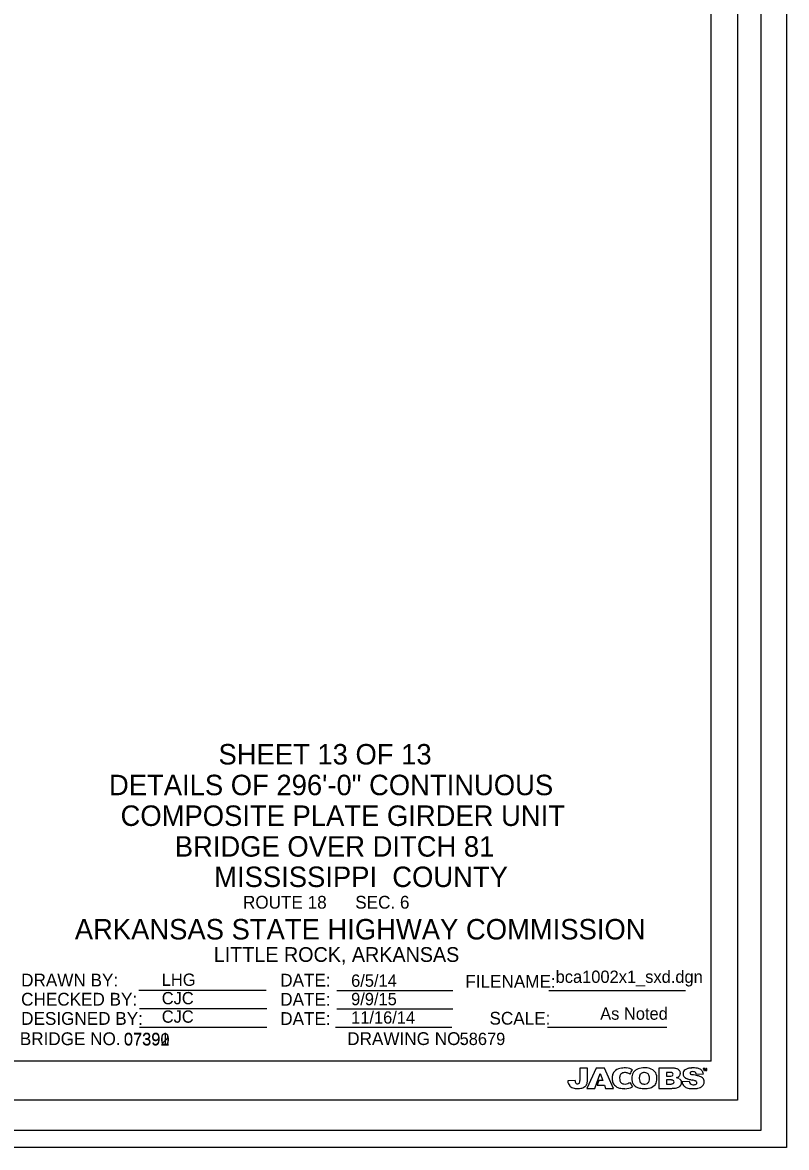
# Model space of a CAD drawing. Extents: x -1771525.9 to -1771483.9, y -422628.9 to -422606.9.
# Drawn here: x -1771498.88 to -1771491.42, y -422628.88 to -422617.89 of the extents above; entities that cross this region are included whole.
import ezdxf

# ---------------------------------------------------------------- set-up
doc = ezdxf.new("R2010")
doc.units = 0
for name, color, linetype in [('border', 7, 'Continuous'), ('Border 2660-Hwy18 - Level 62', 7, 'Continuous'), ('Border 2660-Hwy18 - Level 63', 7, 'Continuous'), ('Border 2660-Hwy18 - Text', 7, 'Continuous'), ('Border 2660-Hwy18 - Title Text', 7, 'Continuous'), ('Bridge No BLFR', 7, 'Continuous'), ('Bridge No BLO', 7, 'Continuous'), ('Bridge No Ditch 81', 7, 'Continuous'), ('Level 62 PDF', 7, 'Continuous'), ('Text', 7, 'Continuous'), ('Title Block Text', 7, 'Continuous'), ('Title Text', 7, 'Continuous')]:
    doc.layers.add(name, color=color, linetype=linetype)

msp = doc.modelspace()

# ---------------------------------------------------------------- linework, layer by layer
at = {"layer": 'border'}
for p, q in [((-1771492.157, -422628.038), (-1771492.157, -422607.492)), ((-1771497.744, -422627.346), (-1771496.501, -422627.346)), ((-1771495.811, -422627.348), (-1771494.677, -422627.348)), ((-1771493.741, -422627.348), (-1771492.405, -422627.348)), ((-1771497.737, -422627.526), (-1771496.494, -422627.526)), ((-1771495.811, -422627.528), (-1771494.677, -422627.528)), ((-1771497.737, -422627.706), (-1771496.494, -422627.706)), ((-1771495.822, -422627.708), (-1771494.688, -422627.708)), ((-1771493.754, -422627.708), (-1771492.588, -422627.708)), ((-1771492.157, -422628.038), (-1771524.168, -422628.038))]:
    msp.add_line(p, q, dxfattribs=at)
for points in [[(-1771493.362, -422628.217), (-1771493.362, -422628.107), (-1771493.437, -422628.107), (-1771493.437, -422628.228)], [(-1771493.24, -422628.16), (-1771493.214, -422628.23), (-1771493.252, -422628.23), (-1771493.268, -422628.273), (-1771493.198, -422628.273), (-1771493.186, -422628.305), (-1771493.109, -422628.305), (-1771493.198, -422628.109), (-1771493.279, -422628.109), (-1771493.369, -422628.305), (-1771493.293, -422628.305), (-1771493.24, -422628.16)], [(-1771492.523, -422628.109), (-1771492.665, -422628.109), (-1771492.665, -422628.305)], [(-1771492.558, -422628.149), (-1771492.591, -422628.149), (-1771492.591, -422628.186)], [(-1771492.3, -422628.167), (-1771492.23, -422628.164)], [(-1771492.219, -422628.111), (-1771492.234, -422628.111), (-1771492.234, -422628.113), (-1771492.228, -422628.113), (-1771492.228, -422628.13), (-1771492.225, -422628.13), (-1771492.225, -422628.113), (-1771492.219, -422628.113), (-1771492.219, -422628.111)], [(-1771492.214, -422628.114), (-1771492.214, -422628.114), (-1771492.208, -422628.13), (-1771492.206, -422628.13), (-1771492.2, -422628.114), (-1771492.2, -422628.114), (-1771492.2, -422628.13), (-1771492.198, -422628.13), (-1771492.198, -422628.111), (-1771492.201, -422628.111), (-1771492.207, -422628.127), (-1771492.213, -422628.111), (-1771492.217, -422628.111), (-1771492.217, -422628.13), (-1771492.214, -422628.13), (-1771492.214, -422628.114)], [(-1771493.484, -422628.229), (-1771493.555, -422628.232)], [(-1771492.591, -422628.186), (-1771492.557, -422628.186)], [(-1771492.554, -422628.223), (-1771492.591, -422628.223), (-1771492.591, -422628.263)], [(-1771492.591, -422628.263), (-1771492.553, -422628.263)], [(-1771492.369, -422628.237), (-1771492.439, -422628.24)], [(-1771492.665, -422628.305), (-1771492.538, -422628.305)]]:
    msp.add_lwpolyline(points, dxfattribs=at)
for centre, radius, start, end in [((-1771493.024, -422628.202), 0.0987, 155.2444, 178.6811), ((-1771493.04, -422628.194), 0.0809, 126.8513, 155.2444), ((-1771493.021, -422628.221), 0.114, 94.7853, 126.8513), ((-1771492.946, -422628.209), 0.104, 161.2834, 178.6702), ((-1771493.021, -422628.184), 0.0243, 134.3139, 161.2834), ((-1771492.999, -422628.206), 0.0556, 110.7655, 134.3139), ((-1771493, -422628.469), 0.363, 86.903, 94.7853), ((-1771493, -422628.204), 0.0529, 91.5073, 110.7655), ((-1771492.998, -422628.267), 0.116, 82.6359, 91.5073), ((-1771492.99, -422628.201), 0.0493, 65.5548, 82.6359), ((-1771492.986, -422628.219), 0.113, 56.9246, 86.903), ((-1771493.019, -422628.264), 0.119, 54.6002, 65.5548), ((-1771492.7, -422628.284), 0.276, 144.635, 154.8844), ((-1771492.831, -422628.205), 0.1, 148.6249, 181.2859), ((-1771492.853, -422628.192), 0.0755, 123.8806, 148.6249), ((-1771492.816, -422628.247), 0.142, 111.7104, 123.8806), ((-1771492.828, -422628.217), 0.109, 96.5371, 111.7104), ((-1771492.766, -422628.207), 0.0917, 160.8611, 181.2981), ((-1771492.826, -422628.186), 0.0287, 136.1177, 160.8611), ((-1771492.809, -422628.203), 0.0518, 117.7176, 136.1177), ((-1771492.796, -422628.489), 0.384, 91.9058, 96.5371), ((-1771492.815, -422628.191), 0.0382, 100.2108, 117.7176), ((-1771492.806, -422628.241), 0.0895, 90.9675, 100.2108), ((-1771492.802, -422628.271), 0.166, 73.4477, 92.4253), ((-1771492.807, -422628.214), 0.0622, 67.077, 90.4218), ((-1771492.798, -422628.192), 0.0386, 24.6274, 67.077), ((-1771492.814, -422628.199), 0.056, 2.7442, 24.6274), ((-1771492.787, -422628.22), 0.112, 41.1934, 73.4477), ((-1771492.746, -422628.184), 0.0579, 18.6966, 41.1934), ((-1771492.815, -422628.207), 0.13, 344.5708, 18.6966), ((-1771492.56, -422628.284), 0.135, 86.2098, 89.3498), ((-1771492.554, -422628.2), 0.0514, 74.8723, 86.2098), ((-1771492.546, -422628.169), 0.0196, 40.2425, 74.8723), ((-1771492.546, -422628.165), 0.0196, 284.1438, 307.8865), ((-1771492.543, -422628.168), 0.0149, 307.8866, 341.4625), ((-1771492.539, -422628.164), 0.0108, 21.9604, 40.2425), ((-1771492.547, -422628.167), 0.0195, 341.4625, 21.9604), ((-1771492.523, -422628.213), 0.104, 72.1885, 90.1477), ((-1771492.51, -422628.171), 0.0603, 61.4844, 72.1885), ((-1771492.508, -422628.168), 0.0564, 34.7868, 61.4844), ((-1771492.501, -422628.153), 0.0471, 296.8412, 329.8182), ((-1771492.488, -422628.154), 0.0315, 16.9455, 34.7868), ((-1771492.487, -422628.161), 0.0307, 329.8182, 347.0949), ((-1771492.501, -422628.158), 0.0455, 347.0949, 16.9455), ((-1771492.383, -422628.164), 0.0476, 124.08, 177.6485), ((-1771492.389, -422628.164), 0.0416, 177.6485, 218.8535), ((-1771492.352, -422628.21), 0.103, 108.2808, 124.08), ((-1771492.359, -422628.189), 0.0811, 99.8173, 108.2808), ((-1771492.331, -422628.348), 0.242, 93.402, 99.8173), ((-1771492.354, -422628.157), 0.00815, 165.3108, 208.2887), ((-1771492.347, -422628.159), 0.016, 146.4706, 165.3108), ((-1771492.347, -422628.152), 0.0169, 211.7417, 226.6339), ((-1771492.353, -422628.155), 0.00877, 130.7855, 146.4706), ((-1771492.342, -422628.168), 0.0256, 97.3055, 130.7855), ((-1771492.349, -422628.154), 0.0145, 226.6339, 245.1429), ((-1771492.332, -422628.117), 0.0549, 245.1429, 260.9806), ((-1771492.331, -422628.359), 0.254, 80.6549, 93.402), ((-1771492.336, -422628.211), 0.0692, 81.3212, 97.3055), ((-1771492.416, -422628.645), 0.479, 77.5139, 80.9806), ((-1771492.331, -422628.178), 0.0359, 57.474, 81.3212), ((-1771492.323, -422628.165), 0.0202, 37.1977, 57.474), ((-1771492.739, -422630.107), 1.977, 76.8035, 77.5139), ((-1771492.335, -422628.174), 0.0351, 11.0051, 37.1977), ((-1771492.304, -422628.197), 0.0897, 57.5906, 80.6549), ((-1771492.282, -422628.163), 0.0494, 39.0736, 57.5906), ((-1771492.292, -422628.171), 0.0612, 6.4385, 39.0736), ((-1771493.433, -422628.223), 0.123, 184.5698, 198.1069), ((-1771493.499, -422628.244), 0.0527, 198.1069, 225.9799), ((-1771493.481, -422628.225), 0.0797, 225.9799, 261.0714), ((-1771493.424, -422628.231), 0.0602, 178.2556, 191.4961), ((-1771493.456, -422628.237), 0.0277, 191.4961, 218.7511), ((-1771493.464, -422628.244), 0.0164, 218.7511, 257.488), ((-1771493.46, -422628.227), 0.0345, 257.488, 275.7834), ((-1771493.46, -422628.235), 0.0257, 275.7834, 301.6926), ((-1771493.452, -422628.247), 0.0122, 301.6926, 325.4171), ((-1771493.466, -422628.238), 0.0285, 325.4171, 349.1575), ((-1771493.516, -422628.228), 0.0792, 349.1575, 360), ((-1771493.443, -422628.213), 0.0931, 279.1616, 305.8646), ((-1771493.423, -422628.241), 0.0585, 305.8646, 338.7843), ((-1771493.418, -422628.243), 0.0527, 338.7843, 350.0951), ((-1771493.907, -422628.157), 0.549, 350.0951, 351.3706), ((-1771493.486, -422628.221), 0.124, 351.3706, 1.8291), ((-1771492.97, -422628.203), 0.153, 178.6811, 194.3912), ((-1771493.062, -422628.227), 0.0582, 194.3912, 214.1799), ((-1771493.005, -422628.188), 0.127, 214.1799, 231.6615), ((-1771493.036, -422628.228), 0.0765, 231.6616, 258.686), ((-1771492.964, -422628.209), 0.0855, 178.6702, 195.8531), ((-1771493.006, -422628.221), 0.0421, 195.8531, 214.5369), ((-1771493.008, -422628.223), 0.0388, 214.5369, 253.1918), ((-1771492.997, -422628.186), 0.0769, 253.1918, 291.1956), ((-1771492.996, -422628.163), 0.146, 268.8163, 299.3878), ((-1771493.003, -422628.171), 0.0928, 291.1956, 305.5144), ((-1771492.586, -422628.064), 0.407, 206.7197, 213.678), ((-1771492.779, -422628.203), 0.152, 181.2859, 193.1956), ((-1771492.861, -422628.223), 0.0683, 193.1956, 217.7499), ((-1771492.828, -422628.196), 0.111, 217.7499, 244.1703), ((-1771492.763, -422628.207), 0.0951, 181.2981, 197.9492), ((-1771492.825, -422628.227), 0.0299, 197.9492, 222.7741), ((-1771492.812, -422628.215), 0.0474, 222.7741, 250.1955), ((-1771492.811, -422628.212), 0.0507, 250.1955, 269.1264), ((-1771492.809, -422628.072), 0.191, 269.1264, 272.0424), ((-1771492.804, -422628.212), 0.0512, 272.0424, 299.5401), ((-1771492.796, -422628.225), 0.036, 299.5401, 342.4003), ((-1771492.849, -422628.208), 0.091, 342.4003, 0.0845), ((-1771493.007, -422628.208), 0.249, 0.0845, 2.7442), ((-1771492.781, -422628.205), 0.101, 285.9017, 322.6714), ((-1771492.756, -422628.223), 0.0698, 322.6714, 344.5708), ((-1771492.557, -422628.122), 0.0633, 270.0363, 284.1438), ((-1771492.558, -422628.47), 0.247, 86.6838, 88.8756), ((-1771492.553, -422628.159), 0.104, 270.0001, 276.6749), ((-1771492.547, -422628.273), 0.0497, 75.9314, 86.6838), ((-1771492.546, -422628.219), 0.043, 276.6749, 293.0645), ((-1771492.543, -422628.257), 0.0328, 59.6202, 75.9314), ((-1771492.536, -422628.243), 0.0178, 293.0645, 337.5037), ((-1771492.534, -422628.241), 0.015, 30.8341, 59.6202), ((-1771492.536, -422628.243), 0.0177, 337.5037, 30.8341), ((-1771492.514, -422628.128), 0.0753, 284.6785, 296.8411), ((-1771492.511, -422628.291), 0.092, 61.0815, 79.9242), ((-1771492.502, -422628.24), 0.0609, 279.6279, 313.6357), ((-1771492.485, -422628.245), 0.039, 44.9773, 61.0815), ((-1771492.495, -422628.247), 0.0511, 313.6357, 342.9845), ((-1771492.489, -422628.249), 0.0452, 342.9845, 44.9773), ((-1771492.063, -422628.187), 0.38, 187.9971, 189.0947), ((-1771492.389, -422628.239), 0.0503, 189.0947, 202.464), ((-1771492.354, -422628.225), 0.0881, 202.464, 215.8926), ((-1771492.375, -422628.24), 0.0621, 215.8926, 243.2968), ((-1771492.377, -422628.154), 0.0566, 218.8535, 233.6549), ((-1771492.364, -422628.136), 0.0797, 233.6549, 244.7689), ((-1771492.331, -422628.066), 0.156, 244.7689, 253.473), ((-1771492.284, -422627.906), 0.323, 253.473, 259.8297), ((-1771492.318, -422628.229), 0.0523, 188.5141, 201.638), ((-1771492.337, -422628.236), 0.0319, 201.638, 242.3635), ((-1771492.331, -422628.225), 0.045, 242.3635, 264.6229), ((-1771492.393, -422628.517), 0.297, 76.0104, 79.8297), ((-1771492.327, -422628.189), 0.0806, 264.6229, 273.901), ((-1771492.325, -422628.223), 0.0464, 273.901, 289.1925), ((-1771492.345, -422628.323), 0.0974, 67.9593, 76.0104), ((-1771492.318, -422628.242), 0.0263, 289.1925, 322.566), ((-1771492.318, -422628.258), 0.0265, 39.9313, 67.9593), ((-1771492.309, -422628.25), 0.0145, 2.1813, 39.9313), ((-1771492.309, -422628.25), 0.0141, 322.566, 2.1813), ((-1771492.325, -422628.341), 0.163, 65.6998, 76.8035), ((-1771492.295, -422628.226), 0.0772, 295.6144, 314.022), ((-1771492.29, -422628.263), 0.0776, 51.3565, 65.6998), ((-1771492.274, -422628.243), 0.0523, 36.5162, 51.3565), ((-1771492.283, -422628.238), 0.0608, 314.022, 345.1611), ((-1771492.271, -422628.241), 0.0486, 345.1611, 36.5162), ((-1771493.455, -422628.063), 0.244, 261.0714, 269.9405), ((-1771493.455, -422628.14), 0.167, 269.9405, 279.1616), ((-1771492.993, -422628.01), 0.298, 258.686, 268.8163), ((-1771492.838, -422628.219), 0.0859, 244.1703, 259.4942), ((-1771492.8, -422628.009), 0.299, 259.4942, 268.6426), ((-1771492.802, -422628.128), 0.18, 268.6426, 285.9017), ((-1771492.548, -422627.967), 0.338, 271.7224, 279.6279), ((-1771492.362, -422628.215), 0.0904, 243.2968, 257.4598), ((-1771492.336, -422628.095), 0.213, 257.4598, 268.8656), ((-1771492.328, -422627.727), 0.581, 268.8656, 270.7612), ((-1771492.323, -422628.131), 0.177, 270.7612, 282.5001), ((-1771492.308, -422628.198), 0.109, 282.5001, 295.6144)]:
    msp.add_arc(centre, radius, start, end, dxfattribs=at)
at = {"layer": 'Border 2660-Hwy18 - Level 62'}
msp.add_lwpolyline([(-1771525.789, -422606.907), (-1771491.67, -422606.907), (-1771491.67, -422628.716), (-1771525.789, -422628.716)], close=True, dxfattribs=at)
at = {"layer": 'Border 2660-Hwy18 - Level 63'}
msp.add_lwpolyline([(-1771525.9, -422607.05), (-1771491.9, -422607.05), (-1771491.9, -422628.419), (-1771525.9, -422628.419)], close=True, dxfattribs=at)
at = {"layer": 'Level 62 PDF'}
msp.add_lwpolyline([(-1771525.539, -422607.073), (-1771491.42, -422607.073), (-1771491.42, -422628.883), (-1771525.539, -422628.883)], close=True, dxfattribs=at)

# ---------------------------------------------------------------- texts
at = {"layer": 'Border 2660-Hwy18 - Text'}
for s, p in [('DRAWN BY:', (-1771498.893, -422627.31)), ('DATE:', (-1771496.363, -422627.311)), ('FILENAME:', (-1771494.556, -422627.323)), ('CHECKED BY:', (-1771498.893, -422627.497)), ('DATE:', (-1771496.363, -422627.498)), ('DESIGNED BY:', (-1771498.893, -422627.685)), ('DATE:', (-1771496.363, -422627.686)), ('SCALE:', (-1771494.32, -422627.683)), ('BRIDGE NO.', (-1771498.906, -422627.883)), ('DRAWING NO.', (-1771495.709, -422627.882))]:
    msp.add_text(s, height=0.125, dxfattribs=at).set_placement(p)
at = {"layer": 'Border 2660-Hwy18 - Title Text'}
for s, height, p in [('MISSISSIPPI  COUNTY', 0.2, (-1771497.008, -422626.339)), ('ROUTE 18      SEC. 6', 0.125, (-1771496.727, -422626.55)), ('ARKANSAS STATE HIGHWAY COMMISSION', 0.2, (-1771498.369, -422626.851)), ('LITTLE ROCK, ARKANSAS', 0.144, (-1771497.012, -422627.07))]:
    msp.add_text(s, height=height, dxfattribs=at).set_placement(p)
at = {"layer": 'Bridge No BLFR'}
msp.add_text('07392', height=0.12, dxfattribs=at).set_placement((-1771497.89, -422627.887))
at = {"layer": 'Bridge No BLO'}
msp.add_text('07391', height=0.12, dxfattribs=at).set_placement((-1771497.89, -422627.882))
at = {"layer": 'Bridge No Ditch 81'}
msp.add_text('07390', height=0.12, dxfattribs=at).set_placement((-1771497.89, -422627.887))
at = {"layer": 'Text'}
for s, p in [('LHG', (-1771497.52, -422627.304)), ('6/5/14', (-1771495.671, -422627.313)), ('CJC', (-1771497.52, -422627.484)), ('9/9/15', (-1771495.671, -422627.493)), ('As Noted', (-1771493.239, -422627.635)), ('CJC', (-1771497.52, -422627.664)), ('11/16/14', (-1771495.671, -422627.673))]:
    msp.add_text(s, height=0.12, dxfattribs=at).set_placement(p)
at = {"layer": 'Title Block Text'}
for s, p in [('bca1002x1_sxd.dgn', (-1771493.674, -422627.275)), ('58679', (-1771494.612, -422627.882))]:
    msp.add_text(s, height=0.12, dxfattribs=at).set_placement(p)
at = {"layer": 'Title Text'}
for s, p in [('SHEET 13 OF 13', (-1771496.966, -422625.142)), ('DETAILS OF 296\'-0" CONTINUOUS', (-1771498.035, -422625.442)), ('COMPOSITE PLATE GIRDER UNIT', (-1771497.922, -422625.742)), ('BRIDGE OVER DITCH 81', (-1771497.393, -422626.042))]:
    msp.add_text(s, height=0.2, dxfattribs=at).set_placement(p)

doc.saveas('drawing.dxf')
